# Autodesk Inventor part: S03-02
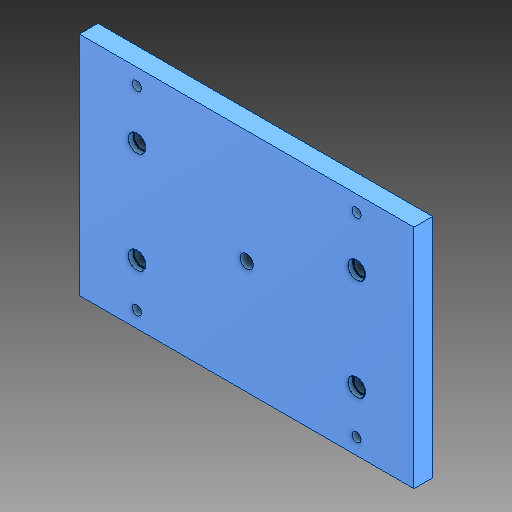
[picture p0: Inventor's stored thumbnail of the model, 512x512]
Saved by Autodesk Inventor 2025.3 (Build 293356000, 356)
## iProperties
Created: 2025-04
Part Number: S03-02
Material: Všeobecné
Document SubType Name: Modeling
Designer: Patrik
Density: 1 g/cm^3
Appearance: Výchozí
Description: Vyhazovaci deska opěrná
Stock Number: F 90/396 396/268/1730
Mass: 2289.65 g
Surface Area: 2494.91 cm^2
Volume: 2289.65 cm^3
User Status: 1730
Author: Patrik
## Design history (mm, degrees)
feature "Base1"
feature "Vyřezání2"
sketch "Náčrt2"
  geometry: C1 r 8 at (198, -134) reference; C2 r 8 at (198, -134) reference; 1 further point
extrude "Vysunutí2" cut sketch "Náčrt2" stored distance "d2" = 10; taper "d3" = 0 deg
feature "Závit1" dims "d4" = 22, "d5" = 0
sketch "Náčrt4"
  geometry: C1 r 8 at (328, 190.03) reference; C2 r 8 at (328, 70.03) reference; C3 r 8 at (68, 190.03) reference; C4 r 8 at (68, 70.03) reference; 1 further point
extrude "Vysunutí4" cut sketch "Náčrt4" stored distance "d8" = 10; taper "d9" = 0 deg
feature "Vyřezání7"
node "Těleso1"
node "Promítnutá smyčka2"
feature "Plocha2"
node "Povrch2"
feature "Plocha12"
node "Povrch12"
